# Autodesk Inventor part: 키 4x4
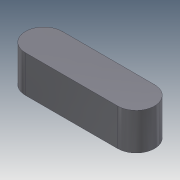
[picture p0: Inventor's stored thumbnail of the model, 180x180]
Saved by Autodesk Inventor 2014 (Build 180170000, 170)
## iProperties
Company: 한국ATC센터
Created: 2014-10
Part Number: 키 4x4
Document SubType Name: Modeling
Designer: KYOUNG IL JANG
Density: 1 g/cm^3
Mass: 0.210265 g
Surface Area: 2.35398 cm^2
Volume: 0.210265 cm^3
Material: 일반
Appearance: 강철 - 광택
Author: KYOUNG IL JANG
Revision Number: 1
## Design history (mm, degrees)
sketch "스케치1"
  geometry: L1 (-5, -2)-(5, -2); L2 (5, 2)-(-5, 2); A1 r 2 centre (5, 0) between (5, -2) and (5, 2); A2 r 2 centre (-5, 0) between (-5, 2) and (-5, -2); 2 further points
  constraints: 4 end point, 4 point on circle, 4 tangent, 2 centre point, 1 horizontal, 1 horizontal alignment, 1 midpoint, 1 parallel, 1 vertical alignment
  dimensions: "d0" = 4 distance between parallel lines of L1 L2; "d1" = 14 dimension on A1 A2
extrude "돌출1" new body sketch "스케치1" stored distance "d2" = 4; taper "d3" = 0 deg
node "솔리드1"
